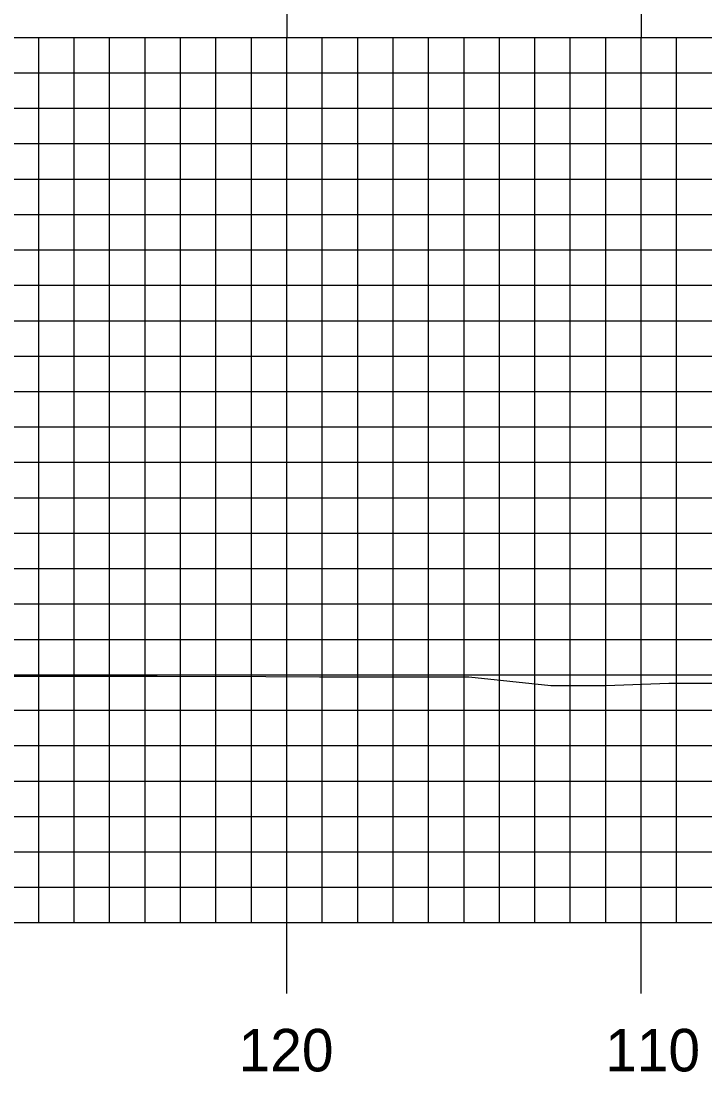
# Model space of a CAD drawing. Extents: x 1763365 to 1763708, y 442591 to 442811.
# Drawn here: x 1763403.31 to 1763422.6, y 442709.45 to 442739.13 of the extents above; entities that cross this region are included whole.
import ezdxf

# ---------------------------------------------------------------- set-up
doc = ezdxf.new("R2010")
doc.units = 0
for name, color, linetype in [('H_V ANNOTATION', 7, 'Continuous'), ('MAJOR', 7, 'Continuous'), ('MINOR', 7, 'Continuous'), ('S_Roadway_Centerline', 7, 'Continuous')]:
    doc.layers.add(name, color=color, linetype=linetype)

msp = doc.modelspace()

# ---------------------------------------------------------------- linework, layer by layer
at = {"layer": 'MAJOR'}
for p, q in [((1763410.805, 442740.669), (1763410.805, 442738.665)), ((1763420.805, 442740.669), (1763420.805, 442738.665)), ((1763390.805, 442738.665), (1763670.805, 442738.665)), ((1763390.805, 442738.665), (1763670.805, 442738.665)), ((1763410.805, 442713.665), (1763410.805, 442738.665)), ((1763420.805, 442713.665), (1763420.805, 442738.665)), ((1763390.805, 442733.665), (1763670.805, 442733.665)), ((1763390.805, 442728.665), (1763670.805, 442728.665)), ((1763390.805, 442723.665), (1763670.805, 442723.665)), ((1763390.805, 442718.665), (1763670.805, 442718.665)), ((1763390.805, 442713.665), (1763670.805, 442713.665)), ((1763390.805, 442713.665), (1763670.805, 442713.665)), ((1763410.805, 442711.661), (1763410.805, 442713.665)), ((1763420.805, 442711.661), (1763420.805, 442713.665))]:
    msp.add_line(p, q, dxfattribs=at)
at = {"layer": 'MINOR'}
for p, q in [((1763403.805, 442713.665), (1763403.805, 442738.665)), ((1763404.805, 442713.665), (1763404.805, 442738.665)), ((1763405.805, 442713.665), (1763405.805, 442738.665)), ((1763406.805, 442713.665), (1763406.805, 442738.665)), ((1763407.805, 442713.665), (1763407.805, 442738.665)), ((1763408.805, 442713.665), (1763408.805, 442738.665)), ((1763409.805, 442713.665), (1763409.805, 442738.665)), ((1763411.805, 442713.665), (1763411.805, 442738.665)), ((1763412.805, 442713.665), (1763412.805, 442738.665)), ((1763413.805, 442713.665), (1763413.805, 442738.665)), ((1763414.805, 442713.665), (1763414.805, 442738.665)), ((1763415.805, 442713.665), (1763415.805, 442738.665)), ((1763416.805, 442713.665), (1763416.805, 442738.665)), ((1763417.805, 442713.665), (1763417.805, 442738.665)), ((1763418.805, 442713.665), (1763418.805, 442738.665)), ((1763419.805, 442713.665), (1763419.805, 442738.665)), ((1763421.805, 442713.665), (1763421.805, 442738.665)), ((1763390.805, 442737.665), (1763670.805, 442737.665)), ((1763390.805, 442736.665), (1763670.805, 442736.665)), ((1763390.805, 442735.665), (1763670.805, 442735.665)), ((1763390.805, 442734.665), (1763670.805, 442734.665)), ((1763390.805, 442732.665), (1763670.805, 442732.665)), ((1763390.805, 442731.665), (1763670.805, 442731.665)), ((1763390.805, 442730.665), (1763670.805, 442730.665)), ((1763390.805, 442729.665), (1763670.805, 442729.665)), ((1763390.805, 442727.665), (1763670.805, 442727.665)), ((1763390.805, 442726.665), (1763670.805, 442726.665)), ((1763390.805, 442725.665), (1763670.805, 442725.665)), ((1763390.805, 442724.665), (1763670.805, 442724.665)), ((1763390.805, 442722.665), (1763670.805, 442722.665)), ((1763390.805, 442721.665), (1763670.805, 442721.665)), ((1763390.805, 442720.665), (1763670.805, 442720.665)), ((1763390.805, 442720.665), (1763670.805, 442720.665)), ((1763390.805, 442719.665), (1763670.805, 442719.665)), ((1763390.805, 442717.665), (1763670.805, 442717.665)), ((1763390.805, 442716.665), (1763670.805, 442716.665)), ((1763390.805, 442715.665), (1763670.805, 442715.665)), ((1763390.805, 442714.665), (1763670.805, 442714.665))]:
    msp.add_line(p, q, dxfattribs=at)
at = {"layer": 'S_Roadway_Centerline'}
msp.add_lwpolyline([(1763402.846, 442720.628), (1763404.216, 442720.627), (1763405.657, 442720.625), (1763407.15, 442720.622), (1763410.211, 442720.615), (1763411.732, 442720.611), (1763413.213, 442720.609), (1763414.624, 442720.608), (1763415.938, 442720.608), (1763418.253, 442720.365), (1763419.806, 442720.363), (1763421.586, 442720.428), (1763422.459, 442720.429), (1763423.406, 442720.429)], dxfattribs=at)

# ---------------------------------------------------------------- texts
at = {"layer": 'H_V ANNOTATION'}
for s, p in [('120', (1763409.446, 442709.465)), ('110', (1763419.789, 442709.465))]:
    msp.add_text(s, height=1.2, dxfattribs=at).set_placement(p)

doc.saveas('drawing.dxf')
